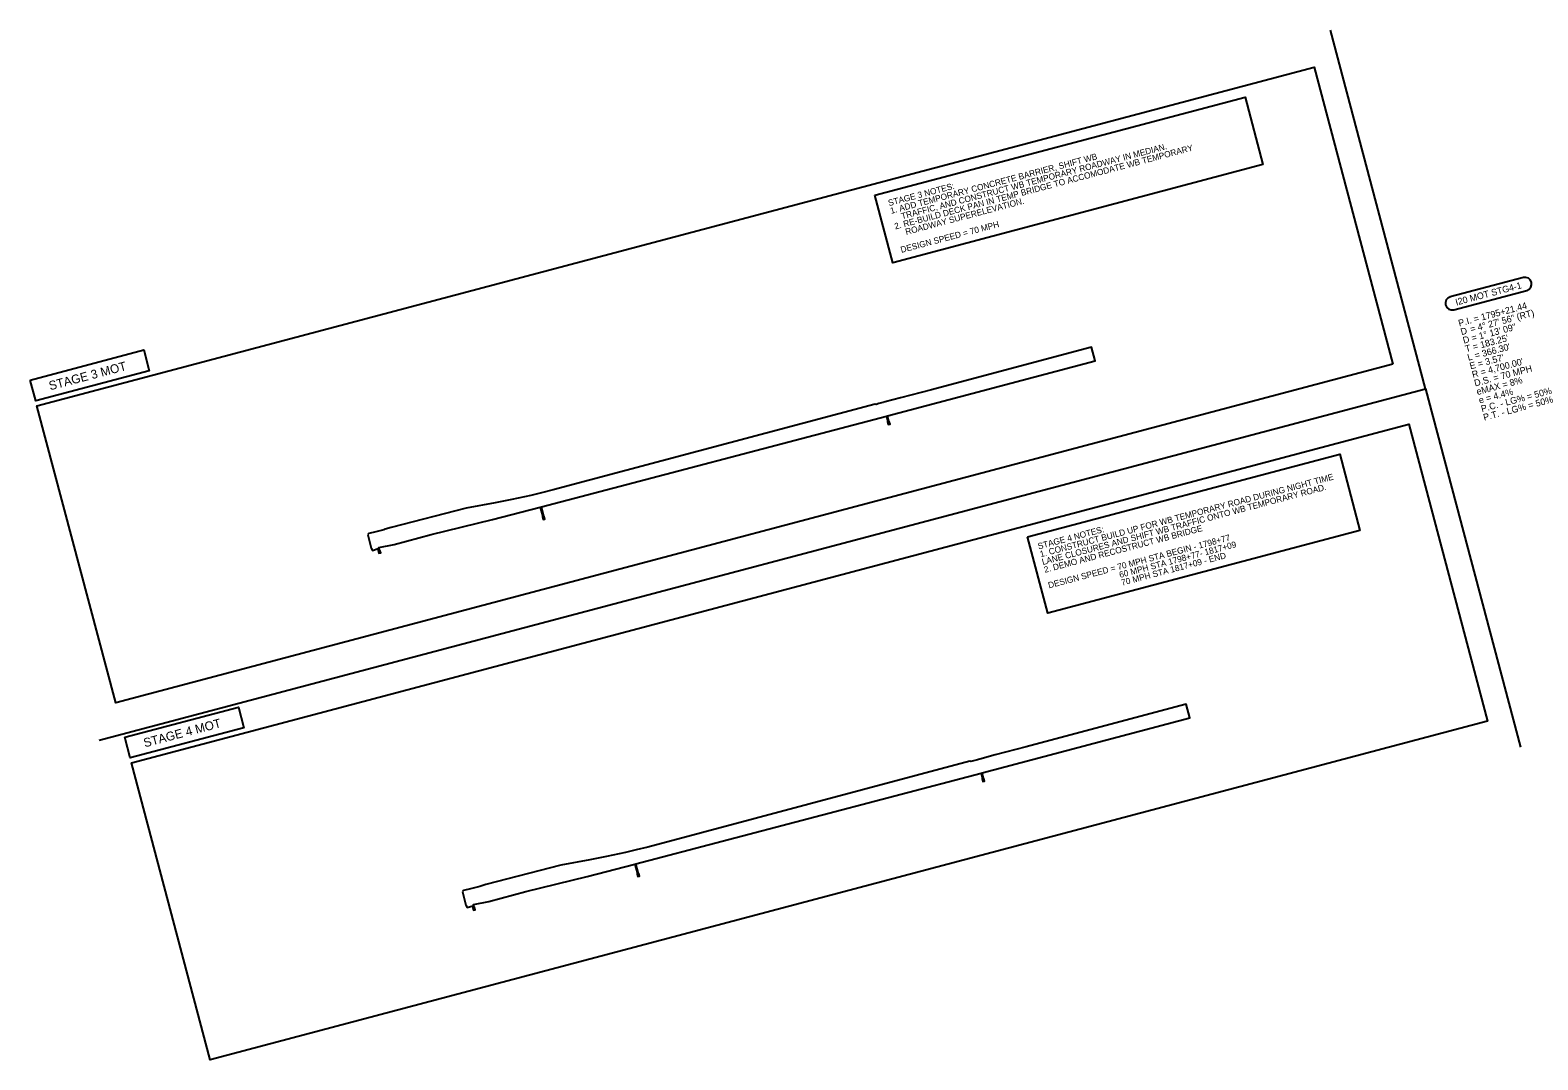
# Model space of a CAD drawing. Extents: x 2108880 to 2119953, y 864865 to 870169.
# Drawn here: x 2108880 to 2115689, y 864865 to 869515 of the extents above; entities that cross this region are included whole.
import ezdxf

# ---------------------------------------------------------------- set-up
doc = ezdxf.new("R2010")
doc.units = 0
for name, color, linetype in [('BR_AUTO DIMENSION', 7, 'Continuous'), ('BR_BORDER LINES', 7, 'Continuous'), ('BR_CENTER LINES', 7, 'Continuous'), ('BR_DETAILS', 7, 'Continuous')]:
    doc.layers.add(name, color=color, linetype=linetype)

msp = doc.modelspace()

# ---------------------------------------------------------------- linework, layer by layer
at = {"layer": 'BR_AUTO DIMENSION'}
msp.add_line((2115182.3, 867896.3), (2114753.1, 869515.4), dxfattribs=at)
for points in [[(2115034.2, 868006.6), (2109265.9, 866477.7), (2108910.4, 867818.9), (2114678.7, 869347.8)], [(2112694.8, 868770.2), (2114367, 869213.5), (2114447.8, 868908.3), (2112775.6, 868465.1)], [(2108879.6, 867935), (2109392.7, 868071), (2109417.6, 867977), (2108904.5, 867841)], [(2115461.6, 866394), (2109693.3, 864865.1), (2109337.8, 866206.4), (2115106.1, 867735.3)], [(2109337.8, 866206.4), (2115106.1, 867735.3), (2115461.6, 866394), (2109693.3, 864865.1)], [(2113384.8, 867227.3), (2114794.4, 867600.9), (2114885.8, 867256.2), (2113476.2, 866882.5)], [(2109307, 866322.5), (2109820.1, 866458.5), (2109845, 866364.5), (2109331.9, 866228.5)]]:
    msp.add_lwpolyline(points, close=True, dxfattribs=at)
msp.add_lwpolyline([(2109191.8, 866308.6), (2115182.3, 867896.3), (2115611.4, 866277.2)], dxfattribs=at)
at = {"layer": 'BR_CENTER LINES'}
for p, q in [((2115623.9, 868398.3), (2115294.1, 868310.9)), ((2115309.5, 868252.9), (2115639.3, 868340.3))]:
    msp.add_line(p, q, dxfattribs=at)
for centre, start, end in [((2115631.6, 868369.3), 284.84478, 104.84478), ((2115301.8, 868281.9), 104.84478, 284.84478)]:
    msp.add_arc(centre, 30, start, end, dxfattribs=at)
at = {"layer": 'BR_DETAILS'}
for points in [[(2110405.4, 867236.7), (2110420.5, 867176.1), (2110425.9, 867166), (2110451.1, 867173.9), (2110453.4, 867165.1), (2110452, 867164.7), (2110455, 867153.1), (2110462.9, 867154.7), (2110459.7, 867166.7), (2110458.2, 867166.3), (2110454.8, 867179.3), (2110523.3, 867192.9), (2110691.2, 867237.4), (2110968.3, 867305.2), (2111183.5, 867361.5), (2111195.3, 867317.1), (2111193.9, 867316.8), (2111197, 867305.2), (2111204.7, 867307.2), (2111201.6, 867318.8), (2111200.2, 867318.4), (2111188.5, 867362.3), (2112747.1, 867772.1), (2112753.9, 867746.6), (2112752.5, 867746.2), (2112755.5, 867734.6), (2112763.3, 867736.7), (2112760.2, 867748.3), (2112758.7, 867747.9), (2112751.9, 867773.5), (2113690.2, 868022.2), (2113673.9, 868083.5), (2113351.5, 867998.1), (2112950.6, 867891.5), (2112811.2, 867854.5), (2112741.3, 867836.1), (2112735.8, 867834.6), (2112733.3, 867834), (2112730.9, 867833.3), (2112713.4, 867828.7), (2112701.1, 867825.5), (2112695.9, 867826.8), (2111242.4, 867438.8), (2111189.6, 867425.5), (2111140.6, 867414.1), (2111055.8, 867395.4), (2110979.5, 867380.4), (2110848.9, 867356.2), (2110509.7, 867269.1), (2110483.1, 867261.1), (2110476.7, 867258.8), (2110441.6, 867249.6), (2110408.8, 867242)], [(2110832.8, 865624.1), (2110847.9, 865563.6), (2110853.3, 865553.4), (2110878.5, 865561.4), (2110880.8, 865552.5), (2110879.4, 865552.1), (2110882.4, 865540.5), (2110890.3, 865542.2), (2110887.1, 865554.2), (2110885.6, 865553.8), (2110882.2, 865566.7), (2110950.7, 865580.4), (2111118.6, 865624.9), (2111395.7, 865692.7), (2111610.9, 865749), (2111622.7, 865704.6), (2111621.3, 865704.2), (2111624.4, 865692.6), (2111632.1, 865694.7), (2111629, 865706.3), (2111627.6, 865705.9), (2111615.9, 865749.7), (2113174.5, 866159.6), (2113181.3, 866134.1), (2113179.9, 866133.7), (2113182.9, 866122.1), (2113190.7, 866124.1), (2113187.6, 866135.7), (2113186.1, 866135.4), (2113179.3, 866161), (2114117.6, 866409.6), (2114101.3, 866471), (2113778.9, 866385.5), (2113378, 866278.9), (2113238.6, 866242), (2113168.7, 866223.5), (2113163.2, 866222.1), (2113160.7, 866221.4), (2113158.3, 866220.8), (2113140.8, 866216.2), (2113128.5, 866212.9), (2113123.3, 866214.3), (2111669.8, 865826.3), (2111617, 865813), (2111568, 865801.6), (2111483.2, 865782.9), (2111406.9, 865767.9), (2111276.3, 865743.7), (2110937.1, 865656.6), (2110910.5, 865648.5), (2110904.1, 865646.3), (2110869, 865637), (2110836.2, 865629.5)]]:
    msp.add_lwpolyline(points, close=True, dxfattribs=at)

# ---------------------------------------------------------------- texts
at = {"layer": 'BR_AUTO DIMENSION'}
for s, p in [('STAGE 3 MOT', (2108970.2, 867888.8)), ('STAGE 4 MOT', (2109397.6, 866276.2))]:
    msp.add_text(s, height=40, rotation=14.84478, dxfattribs=at).set_placement(p)
at = {"layer": 'BR_BORDER LINES'}
for s, p in [('2. RE-BUILD DECK PAN IN TEMP BRIDGE TO ACCOMODATE WB TEMPORARY', (2112787.1, 868615)), ('    TRAFFIC, AND CONSTRUCT WB TEMPORARY ROADWAY IN MEDIAN.', (2112777.7, 868650.2)), ('1. ADD TEMPORARY CONCRETE BARRIER, SHIFT WB ', (2112768.4, 868685.5)), ('STAGE 3 NOTES:', (2112759, 868720.7)), ('    ROADWAY SUPERELEVATION.', (2112796.4, 868579.8)), ('DESIGN SPEED = 70 MPH', (2112815.1, 868509.3)), ('1. CONSTRUCT BUILD UP FOR WB TEMPORARY ROAD DURING NIGHT TIME', (2113444.2, 867134.9)), ('LANE CLOSURES AND SHIFT WB TRAFFIC ONTO WB TEMPORARY ROAD.', (2113453.5, 867099.7)), ('STAGE 4 NOTES:', (2113434.8, 867170.2)), ('2. DEMO AND RECOSTRUCT WB BRIDGE', (2113462.9, 867064.4)), ('DESIGN SPEED = 70 MPH STA BEGIN - 1798+77', (2113481.5, 866994)), ('                               60 MPH STA 1798+77- 1817+09', (2113490.9, 866958.7)), ('                               70 MPH STA 1817+09 - END', (2113500.2, 866923.5))]:
    msp.add_text(s, height=28, rotation=14.84478, dxfattribs=at).set_placement(p)
at = {"layer": 'BR_CENTER LINES'}
for s, p in [('I20 MOT STG4-1', (2115321.4, 868271.5)), ('P.I. = 1795+21.44', (2115334.6, 868176.8)), ('    = 4%%d 27\' 56" (RT)', (2115344.8, 868138.1)), ('D = 1%%d 13\' 09"', (2115355.1, 868099.4)), ('D', (2115344.8, 868138.1)), ("T = 183.25'", (2115365.3, 868060.8)), ("L = 366.30'", (2115375.6, 868022.1)), ("E = 3.57'", (2115385.8, 867983.4)), ("R = 4,700.00'", (2115396.1, 867944.8)), ('D.S. = 70 MPH', (2115406.3, 867906.1)), ('eMAX = 8%', (2115416.6, 867867.4)), ('e = 4.4%', (2115426.8, 867828.8)), ('P.C. - LG% = 50%', (2115437.1, 867790.1)), ('P.T. - LG% = 50%', (2115447.3, 867751.4))]:
    msp.add_text(s, height=30, rotation=14.84478, dxfattribs=at).set_placement(p)

doc.saveas('drawing.dxf')
